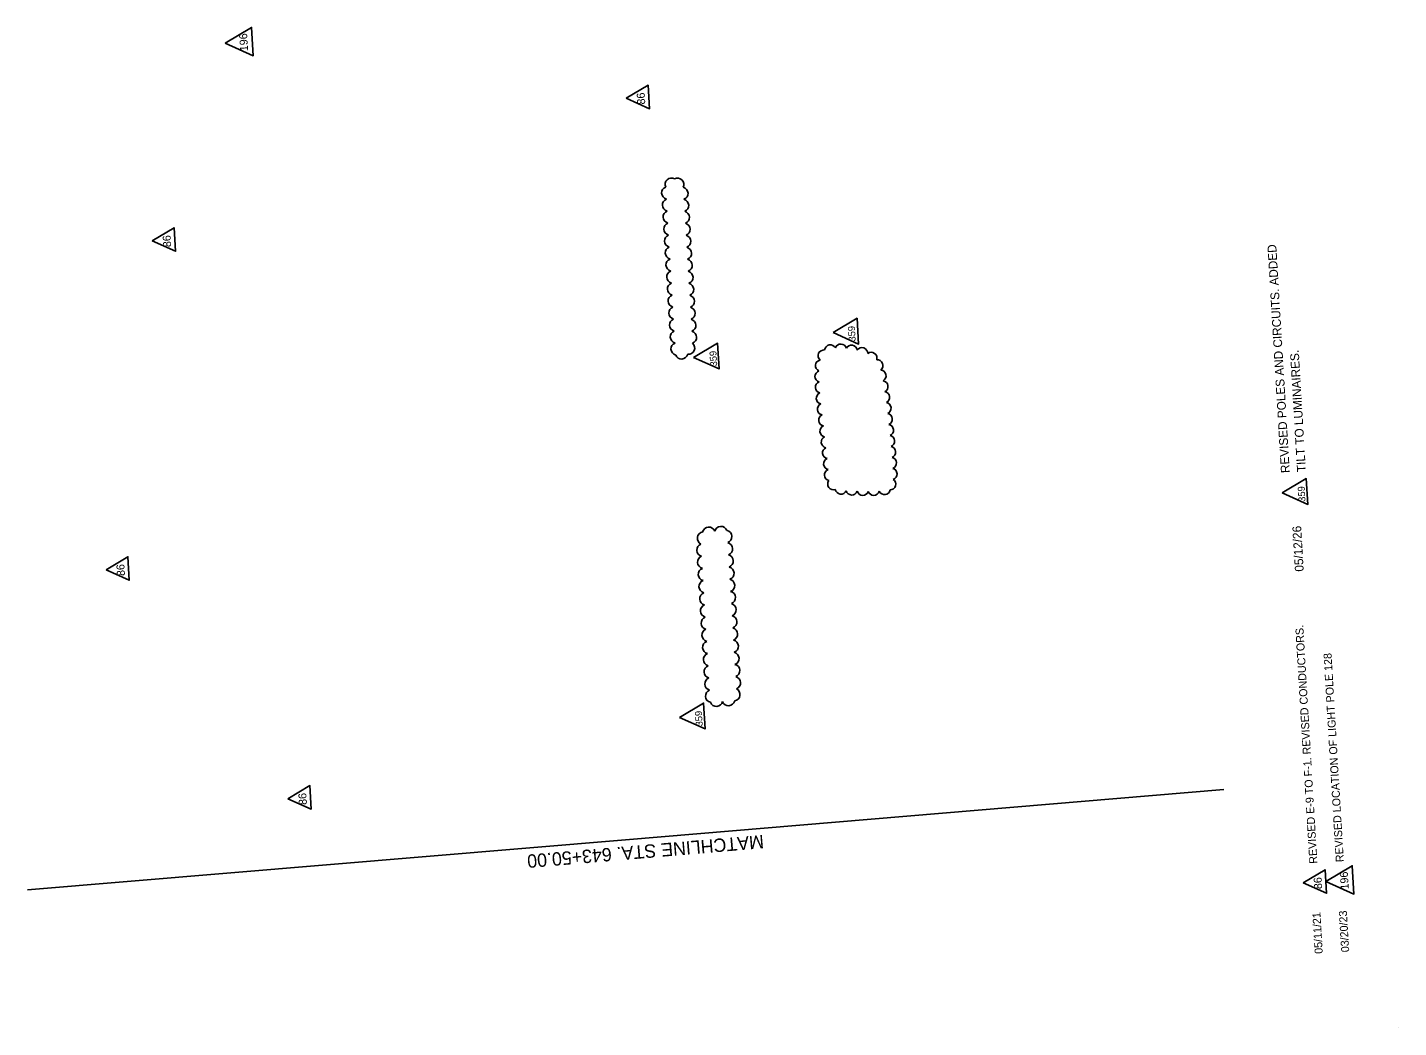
# Model space of a CAD drawing. Extents: x 928602 to 929490, y 640080 to 641338.
# Drawn here: x 928667 to 929490, y 640080 to 640679 of the extents above; entities that cross this region are included whole.
import ezdxf

# ---------------------------------------------------------------- set-up
doc = ezdxf.new("R2010")
doc.units = 0
for name, color, linetype in [('PlotBorder_dp', 7, 'Continuous'), ('ScratchEle_dp', 7, 'Continuous'), ('TextMinor', 7, 'Continuous')]:
    doc.layers.add(name, color=color, linetype=linetype)

msp = doc.modelspace()

# ---------------------------------------------------------------- linework, layer by layer
at = {"layer": 'PlotBorder_dp'}
msp.add_lwpolyline([(929384.91, 640222.63), (929026.17, 640192.5), (928667.43, 640162.36)], dxfattribs=at)
at = {"layer": 'ScratchEle_dp'}
for points in [[(928786, 640669.89), (928802.89, 640662.36), (928801.87, 640679.38)], [(929026.58, 640636.89), (929040.53, 640630.67), (929039.7, 640644.73)], [(928742.28, 640551.42), (928756.24, 640545.2), (928755.4, 640559.26)], [(929150.55, 640496.43), (929165.9, 640489.59), (929164.98, 640505.05)], [(929066.88, 640481.48), (929082.24, 640474.64), (929081.31, 640490.1)], [(929419.94, 640400.33), (929435.29, 640393.49), (929434.37, 640408.95)], [(928714.58, 640354.29), (928728.54, 640348.06), (928727.7, 640362.12)], [(929058.46, 640265.72), (929073.81, 640258.88), (929072.89, 640274.34)], [(928823.68, 640217.07), (928837.64, 640210.85), (928836.8, 640224.9)], [(929432.52, 640166.61), (929446.48, 640160.39), (929445.64, 640174.45)], [(929446.06, 640167.42), (929462.95, 640159.89), (929461.94, 640176.9)]]:
    msp.add_lwpolyline(points, close=True, dxfattribs=at)
for centre, radius, start, end in [((929051.55, 640580.19), 3.78, 110.91308, 255.91308), ((929053.63, 640585.3), 3.78, 59.80785, 204.80785), ((929057.33, 640585.25), 3.78, 333.47758, 118.47758), ((929051.98, 640573), 3.78, 110.91308, 255.91308), ((929059.8, 640579.89), 3.78, 290.91308, 75.91308), ((929060.23, 640572.7), 3.78, 290.91308, 75.91308), ((929052.41, 640565.8), 3.78, 110.91308, 255.91308), ((929060.66, 640565.51), 3.78, 290.91308, 75.91308), ((929052.84, 640558.61), 3.78, 110.91308, 255.91308), ((929061.08, 640558.31), 3.78, 290.91308, 75.91308), ((929053.27, 640551.42), 3.78, 110.91308, 255.91308), ((929061.51, 640551.12), 3.78, 290.91308, 75.91308), ((929053.7, 640544.22), 3.78, 110.91308, 255.91308), ((929061.94, 640543.93), 3.78, 290.91308, 75.91308), ((929054.13, 640537.03), 3.78, 110.91308, 255.91308), ((929062.37, 640536.73), 3.78, 290.91308, 75.91308), ((929054.56, 640529.84), 3.78, 110.91308, 255.91308), ((929054.99, 640522.64), 3.78, 110.91308, 255.91308), ((929062.8, 640529.54), 3.78, 290.91308, 75.91308), ((929055.42, 640515.45), 3.78, 110.91308, 255.91308), ((929063.23, 640522.35), 3.78, 290.91308, 75.91308), ((929063.66, 640515.15), 3.78, 290.91308, 75.91308), ((929055.84, 640508.26), 3.78, 110.91308, 255.91308), ((929064.09, 640507.96), 3.78, 290.91308, 75.91308), ((929056.27, 640501.06), 3.78, 110.91308, 255.91308), ((929064.52, 640500.76), 3.78, 290.91308, 75.91308), ((929056.7, 640493.87), 3.78, 110.91308, 255.91308), ((929064.95, 640493.57), 3.78, 290.91308, 75.91308), ((929057.13, 640486.68), 3.78, 110.91308, 255.91308), ((929063.81, 640487.2), 3.78, 263.87088, 48.87088), ((929145.07, 640482.61), 3.46, 83.17929, 228.17929), ((929148.92, 640485.66), 3.46, 28.57575, 173.57575), ((929155.22, 640486.14), 3.46, 15.23016, 160.23016), ((929161.64, 640485.48), 3.46, 8.03684, 153.03684), ((929167.89, 640483.97), 3.46, 359.71295, 144.71295), ((929059.74, 640484.36), 3.78, 200.91308, 345.91308), ((929143.48, 640476.64), 3.46, 101.88535, 246.88535), ((929173.44, 640481.19), 3.46, 342.13513, 127.13513), ((929177.04, 640476.68), 3.46, 310.05535, 95.05535), ((929143.18, 640470.17), 3.46, 107.85776, 252.85776), ((929178.91, 640470.59), 3.46, 299.09434, 84.09434), ((929143.4, 640463.63), 3.46, 111.00238, 256.00238), ((929180.09, 640464.14), 3.46, 296.53963, 81.53963), ((929181.05, 640457.64), 3.46, 295.23269, 80.23269), ((929143.91, 640457.08), 3.46, 113.00929, 258.00929), ((929144.61, 640450.54), 3.46, 114.14604, 259.14604), ((929181.89, 640451.1), 3.46, 294.40301, 79.40301), ((929145.38, 640443.98), 3.46, 114.2107, 259.2107), ((929182.64, 640444.56), 3.46, 293.81622, 78.81622), ((929146.15, 640437.43), 3.46, 114.2107, 259.2107), ((929183.35, 640438), 3.46, 293.38397, 78.38397), ((929146.92, 640430.87), 3.46, 114.2107, 259.2107), ((929147.69, 640424.32), 3.46, 114.2107, 259.2107), ((929184, 640431.44), 3.46, 292.98055, 77.98055), ((929184.6, 640424.87), 3.46, 292.413, 77.413), ((929148.37, 640417.72), 3.46, 112.54179, 257.54179), ((929185.11, 640418.31), 3.46, 291.50856, 76.50856), ((929148.86, 640411.11), 3.46, 110.91388, 255.91388), ((929185.46, 640411.75), 3.46, 289.68779, 74.68779), ((929150.8, 640405.69), 3.46, 143.50212, 288.50212), ((929184.72, 640405.6), 3.46, 271.49102, 56.49102), ((929155.3, 640403.07), 3.46, 191.04163, 336.04163), ((929161.8, 640402.56), 3.46, 194.90744, 339.90744), ((929168.37, 640402.35), 3.46, 196.40865, 341.40865), ((929174.94, 640402.34), 3.46, 198.37288, 343.37288), ((929181.41, 640402.78), 3.46, 204.44796, 349.44796), ((929076.08, 640376.04), 3.83, 20.91308, 165.91308), ((929083.38, 640376.47), 3.83, 20.91308, 165.91308), ((929072.98, 640373.19), 3.83, 99.20788, 244.20788), ((929086.03, 640374.12), 3.83, 290.91308, 75.91308), ((929086.47, 640366.82), 3.83, 290.91308, 75.91308), ((929072.68, 640366.16), 3.83, 110.91308, 255.91308), ((929073.12, 640358.86), 3.83, 110.91308, 255.91308), ((929086.9, 640359.53), 3.83, 290.91308, 75.91308), ((929073.55, 640351.56), 3.83, 110.91308, 255.91308), ((929087.34, 640352.23), 3.83, 290.91308, 75.91308), ((929073.99, 640344.26), 3.83, 110.91308, 255.91308), ((929087.77, 640344.93), 3.83, 290.91308, 75.91308), ((929074.42, 640336.96), 3.83, 110.91308, 255.91308), ((929088.21, 640337.63), 3.83, 290.91308, 75.91308), ((929074.86, 640329.66), 3.83, 110.91308, 255.91308), ((929088.64, 640330.33), 3.83, 290.91308, 75.91308), ((929075.29, 640322.36), 3.83, 110.91308, 255.91308), ((929089.08, 640323.03), 3.83, 290.91308, 75.91308), ((929075.73, 640315.06), 3.83, 110.91308, 255.91308), ((929089.51, 640315.73), 3.83, 290.91308, 75.91308), ((929076.16, 640307.76), 3.83, 110.91308, 255.91308), ((929089.95, 640308.43), 3.83, 290.91308, 75.91308), ((929090.38, 640301.13), 3.83, 290.91308, 75.91308), ((929076.6, 640300.46), 3.83, 110.91308, 255.91308), ((929077.03, 640293.16), 3.83, 110.91308, 255.91308), ((929090.82, 640293.83), 3.83, 290.91308, 75.91308), ((929077.47, 640285.87), 3.83, 110.91308, 255.91308), ((929091.26, 640286.53), 3.83, 290.91308, 75.91308), ((929077.9, 640278.57), 3.83, 110.91308, 255.91308), ((929090.96, 640279.5), 3.83, 279.20788, 64.20788), ((929080.55, 640276.22), 3.83, 200.91308, 345.91308), ((929087.85, 640276.65), 3.83, 200.91308, 345.91308)]:
    msp.add_arc(centre, radius, start, end, dxfattribs=at)
at = {"layer": 'TextMinor'}
msp.add_line((929489.69, 640079.89), (929489.69, 640079.89), dxfattribs=at)

# ---------------------------------------------------------------- texts
at = {"layer": 'PlotBorder_dp'}
msp.add_text('MATCHLINE STA. 643+50.00', height=8, rotation=184.80152, dxfattribs=at).set_placement((929108.72, 640195.42))
at = {"layer": 'ScratchEle_dp'}
for s, height, p in [('196', 4.8, (928799.79, 640665.27)), ('86', 4.8, (929037.96, 640633.3)), ('86', 4.8, (928753.67, 640547.83)), ('REVISED POLES AND CIRCUITS. ADDED ', 5.28, (929424.48, 640412.43)), ('359', 4.18, (929164.15, 640491.23)), ('359', 4.18, (929081.12, 640476.32)), ('TILT TO LUMINAIRES.', 5.28, (929434.15, 640413)), ('359', 4.18, (929433.9, 640395.15)), ('05/12/26', 5.28, (929432.86, 640353.34)), ('86', 4.8, (928725.96, 640350.69)), ('REVISED E-9 TO F-1. REVISED CONDUCTORS.', 4.8, (929441.03, 640178.23)), ('REVISED LOCATION OF LIGHT POLE 128', 4.8, (929456.9, 640179.17)), ('359', 4.18, (929072.43, 640260.54)), ('86', 4.8, (928835.06, 640213.48)), ('196', 4.8, (929459.85, 640162.79)), ('86', 4.8, (929443.91, 640163.02)), ('05/11/21', 4.8, (929444.25, 640124.24)), ('03/20/23', 4.8, (929460.12, 640125.19))]:
    msp.add_text(s, height=height, rotation=93.41308, dxfattribs=at).set_placement(p)

doc.saveas('drawing.dxf')
